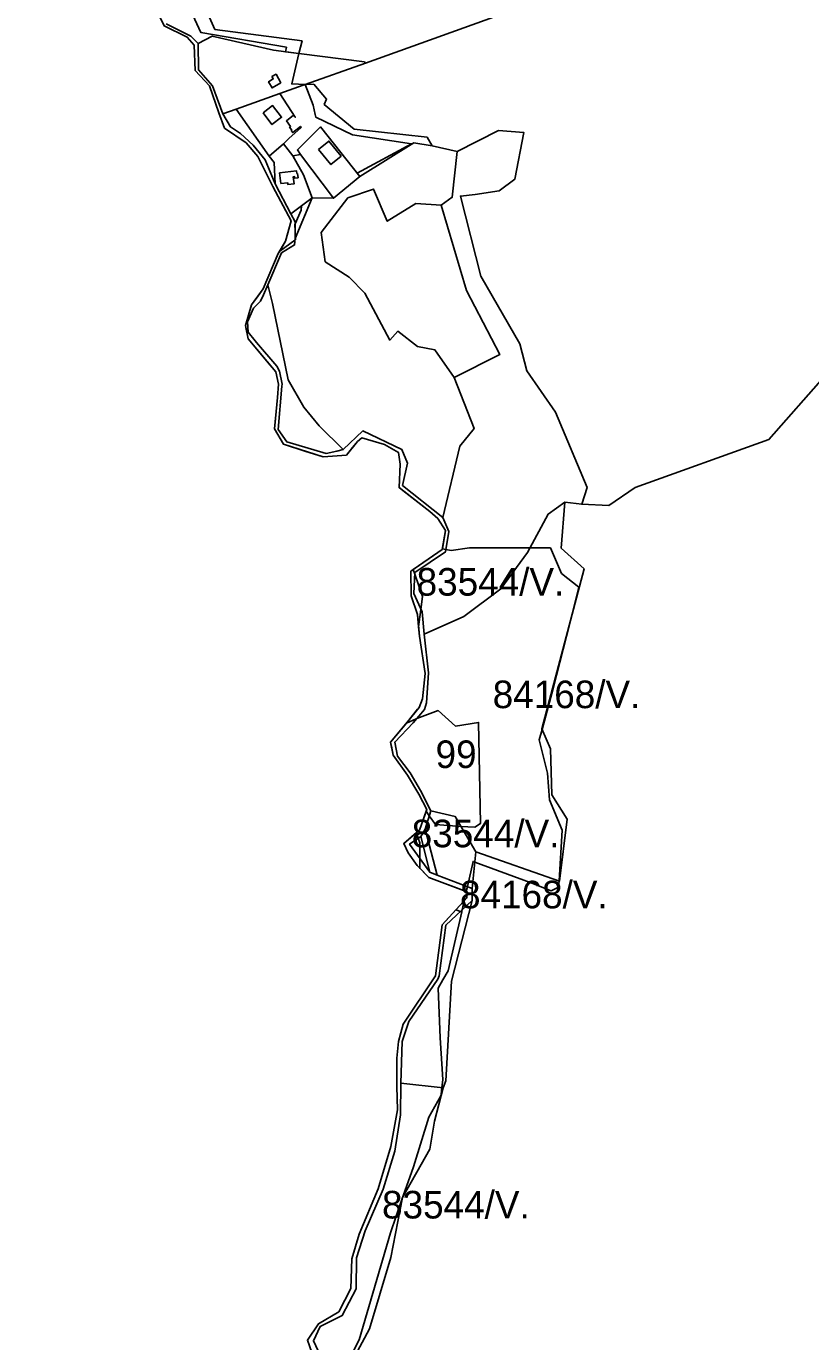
# Model space of a CAD drawing. Extents: x -477304 to -465429, y -1159113 to -1149210.
# Drawn here: x -476469 to -476043, y -1154135 to -1153420 of the extents above; entities that cross this region are included whole.
import ezdxf

# ---------------------------------------------------------------- set-up
doc = ezdxf.new("R2010")
doc.units = 0
for name, color, linetype in [('BPEJ_s', 7, 'Continuous'), ('PUPFL_s', 7, 'Continuous'), ('trav_porost_s', 7, 'Continuous'), ('voda_s', 7, 'Continuous'), ('zahrada_s', 7, 'Continuous')]:
    doc.layers.add(name, color=color, linetype=linetype)

msp = doc.modelspace()

# ---------------------------------------------------------------- linework, layer by layer
at = {"layer": 'BPEJ_s'}
for p, q in [((-476331.66, -1153541.75), (-476331.65, -1153541.75)), ((-476341.64, -1153563.62), (-476343.36, -1153566.03)), ((-476350.28, -1153582.25), (-476350.08, -1153583.28)), ((-476329.6, -1153646.76), (-476317.5, -1153650.64)), ((-476295.43, -1153652.79), (-476292.04, -1153648.55)), ((-476266.79, -1153670.31), (-476264.7, -1153671.95))]:
    msp.add_line(p, q, dxfattribs=at)
for points in [[(-476469.44, -1153302.84), (-476465.62, -1153305.59), (-476462.52, -1153314.71), (-476461.47, -1153317.8), (-476462.31, -1153337.1), (-476459.47, -1153347.25), (-476453.13, -1153354.27), (-476434.77, -1153364.18), (-476417.39, -1153374.78), (-476413.17, -1153379.06), (-476396.78, -1153414.37), (-476394.56, -1153419.33), (-476381.89, -1153425.52), (-476378.24, -1153429.87), (-476377.6, -1153443.54), (-476369.87, -1153451.92), (-476364.68, -1153466.61), (-476361.59, -1153474.95), (-476349.92, -1153482.92), (-476343.55, -1153490.4), (-476335.45, -1153506.67), (-476325.49, -1153525.38), (-476328.44, -1153536.44), (-476331.66, -1153541.75)], [(-476313.98, -1153512.84), (-476302.48, -1153513.07), (-476288.12, -1153501.24), (-476289.5, -1153499.5), (-476260, -1153483.5), (-476292, -1153478.5), (-476312, -1153469), (-476312.32, -1153467.61), (-476313.5, -1153462.5), (-476317.75, -1153451.14), (-476325.15, -1153450.94), (-476321.25, -1153434.31), (-476328.55, -1153433.37), (-476328, -1153431), (-476374.5, -1153423), (-476383.5, -1153403.5)], [(-476383.5, -1153403.5), (-476374.5, -1153423), (-476328, -1153431), (-476328.55, -1153433.37), (-476321.25, -1153434.31), (-476325.15, -1153450.94), (-476317.75, -1153451.14), (-476313.5, -1153462.5), (-476312.32, -1153467.61), (-476312, -1153469), (-476292, -1153478.5), (-476260, -1153483.5), (-476289.5, -1153499.5), (-476288.12, -1153501.24), (-476302.48, -1153513.07), (-476313.98, -1153512.84), (-476319.74, -1153517.13), (-476320, -1153519.5), (-476323.24, -1153526.91), (-476323.5, -1153527.5), (-476323.29, -1153530.85), (-476323.07, -1153534.31), (-476323, -1153535.5), (-476323.4, -1153535.79), (-476331.65, -1153541.75), (-476331.66, -1153541.75), (-476332.5, -1153543.15), (-476340.68, -1153562.28), (-476341.64, -1153563.62)], [(-476331.65, -1153541.75), (-476323.4, -1153535.79), (-476323, -1153535.5), (-476323.07, -1153534.31), (-476323.29, -1153530.85), (-476323.5, -1153527.5), (-476323.24, -1153526.91), (-476320, -1153519.5), (-476319.74, -1153517.13), (-476313.98, -1153512.84)], [(-476343.36, -1153566.03), (-476346.92, -1153571), (-476350.28, -1153582.25)], [(-476350.08, -1153583.28), (-476348.88, -1153589.54), (-476336.83, -1153603.79), (-476333.7, -1153607.49), (-476332.24, -1153614.05), (-476332.85, -1153621.28), (-476333.96, -1153632.7), (-476334.52, -1153638.44), (-476329.6, -1153646.76)], [(-476292.04, -1153648.55), (-476289.45, -1153645.32), (-476287.06, -1153643.2), (-476280.85, -1153645.09), (-476274.67, -1153646.97), (-476267.13, -1153651.17), (-476266.15, -1153657.52), (-476266.79, -1153670.31)], [(-476317.5, -1153650.64), (-476308.09, -1153653.66), (-476295.43, -1153652.79)], [(-476264.7, -1153671.95), (-476250.12, -1153683.41), (-476245.71, -1153687.07), (-476241.45, -1153693.6), (-476243.23, -1153703.64), (-476241.36, -1153703.98), (-476238.5, -1153704.5), (-476228.5, -1153703), (-476195.54, -1153703), (-476184.5, -1153703), (-476178.5, -1153717), (-476169, -1153724.5), (-476174, -1153744.13), (-476183, -1153779.5), (-476188.98, -1153801.84), (-476190.5, -1153807.5), (-476186, -1153825.5), (-476185, -1153840), (-476178, -1153856.5), (-476179.78, -1153884.14), (-476180, -1153887.5), (-476184, -1153889.5), (-476195.5, -1153885), (-476225.55, -1153873.85), (-476226.5, -1153873.5), (-476229.61, -1153887.2), (-476230.21, -1153889.83), (-476229.75, -1153890), (-476229.85, -1153893.33), (-476231.38, -1153895), (-476232.49, -1153899.88), (-476232.58, -1153900.3), (-476232.72, -1153900.93), (-476240, -1153933), (-476242.88, -1153937.97), (-476245.5, -1153942.5), (-476244.5, -1153969.5), (-476243, -1153992), (-476243.51, -1153996.6), (-476243.89, -1154000), (-476244, -1154001), (-476250.5, -1154012.5), (-476259, -1154039.5), (-476264.51, -1154055.36), (-476265.2, -1154057.35), (-476271.5, -1154075.5), (-476288.5, -1154133.5), (-476300, -1154156.5)], [(-476314.26, -1154140.55), (-476316.58, -1154133.74), (-476310.59, -1154124.87), (-476299.56, -1154118.31), (-476292.99, -1154105.63), (-476292.36, -1154089.54), (-476288.4, -1154076.16), (-476278.16, -1154051.5), (-476271.3, -1154028.49), (-476267.65, -1154008.59), (-476267.97, -1153995.89), (-476267.95, -1153980.53), (-476266.98, -1153971.37), (-476264.6, -1153962.05), (-476247.01, -1153935.72), (-476243.39, -1153908.08), (-476235.86, -1153899.88), (-476233.38, -1153900.71), (-476232.72, -1153900.93), (-476240, -1153933), (-476242.88, -1153937.97), (-476245.5, -1153942.5), (-476244.5, -1153969.5), (-476243, -1153992), (-476243.51, -1153996.6), (-476243.89, -1154000), (-476244, -1154001), (-476250.5, -1154012.5), (-476259, -1154039.5), (-476264.51, -1154055.36), (-476265.2, -1154057.35), (-476271.5, -1154075.5), (-476288.5, -1154133.5), (-476300, -1154156.5)]]:
    msp.add_lwpolyline(points, dxfattribs=at)
for points in [[(-476184.5, -1153703), (-476178.5, -1153717), (-476169, -1153724.5), (-476174, -1153744.13), (-476183, -1153779.5), (-476188.98, -1153801.84), (-476190.5, -1153807.5), (-476186, -1153825.5), (-476185, -1153840), (-476178, -1153856.5), (-476179.78, -1153884.14), (-476180, -1153887.5), (-476184, -1153889.5), (-476195.5, -1153885), (-476225.55, -1153873.85), (-476226.5, -1153873.5), (-476229.61, -1153887.2), (-476230.21, -1153889.83), (-476250.63, -1153882.24), (-476255.5, -1153877.23), (-476255.5, -1153871.86), (-476255.5, -1153863.5), (-476256.3, -1153860.82), (-476257.2, -1153857.82), (-476257.2, -1153857.81), (-476255.66, -1153856.52), (-476252.04, -1153846.26), (-476250.34, -1153848.7), (-476247, -1153853.5), (-476233.1, -1153854.47), (-476225.5, -1153855), (-476222.5, -1153853), (-476223.5, -1153798), (-476236, -1153800), (-476245.5, -1153791.5), (-476257.06, -1153795.84), (-476257.5, -1153796), (-476262.73, -1153798.38), (-476262.11, -1153797.64), (-476256.66, -1153790.83), (-476255.82, -1153789.78), (-476254.09, -1153785.08), (-476252.59, -1153771.37), (-476255.67, -1153751.15), (-476256.14, -1153745.96), (-476254.91, -1153736.54), (-476254, -1153729.5), (-476258.23, -1153717.36), (-476259.11, -1153714.85), (-476243.28, -1153703.95), (-476243.23, -1153703.64), (-476241.36, -1153703.98), (-476238.5, -1153704.5), (-476228.5, -1153703), (-476195.54, -1153703)], [(-476254.91, -1153736.54), (-476256.14, -1153745.96), (-476256.74, -1153739.27), (-476260.12, -1153729.15), (-476260.43, -1153715.76), (-476259.11, -1153714.85), (-476258.23, -1153717.36), (-476254, -1153729.5)], [(-476252.04, -1153846.26), (-476251.68, -1153845.24), (-476256.07, -1153836.98), (-476262.17, -1153826.66), (-476269.89, -1153815.72), (-476270.88, -1153810.88), (-476271.34, -1153808.63), (-476262.73, -1153798.38), (-476257.5, -1153796), (-476257.06, -1153795.84), (-476245.5, -1153791.5), (-476236, -1153800), (-476223.5, -1153798), (-476222.5, -1153853), (-476225.5, -1153855), (-476233.1, -1153854.47), (-476247, -1153853.5), (-476250.34, -1153848.7)], [(-476255.5, -1153871.86), (-476255.5, -1153877.23), (-476256.86, -1153875.83), (-476261.88, -1153868.81), (-476264.24, -1153863.72), (-476257.2, -1153857.81), (-476257.2, -1153857.82), (-476256.3, -1153860.82), (-476255.5, -1153863.5)], [(-476232.58, -1153900.3), (-476232.72, -1153900.93), (-476233.38, -1153900.71), (-476235.86, -1153899.88), (-476231.38, -1153895), (-476232.49, -1153899.88)]]:
    msp.add_lwpolyline(points, close=True, dxfattribs=at)
at = {"layer": 'PUPFL_s'}
for points in [[(-476374.39, -1153404.56), (-476352.66, -1153405.48), (-476340.75, -1153395.62), (-476330.21, -1153398.6), (-476316.6, -1153401.84), (-476291.35, -1153405.58), (-476257.17, -1153402.62), (-476217.27, -1153401.74), (-476154.38, -1153379.72), (-476139.88, -1153376.51), (-476120.34, -1153379.11), (-476083.36, -1153366.41), (-476082.77, -1153366.77), (-476285.01, -1153439.63), (-476285.61, -1153438.87), (-476321.25, -1153434.31), (-476319.45, -1153427.4), (-476366.92, -1153421.26)], [(-476253.14, -1153750), (-476254.28, -1153737.93), (-476258.82, -1153727.98), (-476258.19, -1153716.55), (-476241.6, -1153705.3), (-476239.62, -1153694.23), (-476242.91, -1153686.53), (-476233.77, -1153647.74), (-476225.88, -1153638.26), (-476236.79, -1153610.55), (-476211.96, -1153597.98), (-476230.14, -1153563.14), (-476243.89, -1153516.72), (-476237.88, -1153512.5), (-476235.18, -1153487.63), (-476212.73, -1153476.14), (-476198.92, -1153477.35), (-476203.82, -1153502.73), (-476212.39, -1153509.02), (-476225.3, -1153511.01), (-476233.44, -1153511.83), (-476222.33, -1153555.36), (-476201.12, -1153592.18), (-476197.37, -1153606.95), (-476181.77, -1153629.24), (-476164.54, -1153670.32), (-476167.46, -1153679.41), (-476176.7, -1153678.16), (-476185.68, -1153684.75), (-476196.99, -1153705.68), (-476211.47, -1153725.45), (-476231.5, -1153740.34)], [(-476309.17, -1153531.74), (-476306.89, -1153547.56), (-476293.85, -1153555.93), (-476285.32, -1153564.73), (-476271.82, -1153590.14), (-476267.39, -1153585.34), (-476256.69, -1153593.65), (-476247.25, -1153595.5), (-476236.79, -1153610.55), (-476225.88, -1153638.26), (-476233.77, -1153647.74), (-476242.91, -1153686.53), (-476264.81, -1153669.17), (-476262.19, -1153657), (-476265.21, -1153649.58), (-476286.41, -1153639.51), (-476297.08, -1153649.67), (-476310.27, -1153636.72), (-476318.59, -1153626.69), (-476327.06, -1153611.84), (-476335.5, -1153570.35), (-476338.18, -1153560.15), (-476330.64, -1153542.74), (-476323.6, -1153538.43), (-476323.34, -1153534.94), (-476313.98, -1153512.84), (-476318.75, -1153500.26), (-476324.58, -1153490.06), (-476320.27, -1153489.18), (-476302.48, -1153513.07), (-476288.12, -1153501.24), (-476258.77, -1153482.88), (-476248.74, -1153484.62), (-476235.18, -1153487.63), (-476237.88, -1153512.5), (-476243.89, -1153516.72), (-476257.69, -1153515.98), (-476273.17, -1153525.52), (-476280.65, -1153508.04), (-476294.54, -1153512.91)], [(-476309.17, -1153531.74), (-476294.54, -1153512.91), (-476280.65, -1153508.04), (-476273.17, -1153525.52), (-476257.69, -1153515.98), (-476243.89, -1153516.72), (-476230.14, -1153563.14), (-476211.96, -1153597.98), (-476236.79, -1153610.55), (-476247.25, -1153595.5), (-476256.69, -1153593.65), (-476267.39, -1153585.34), (-476271.82, -1153590.14), (-476285.32, -1153564.73), (-476293.85, -1153555.93), (-476306.89, -1153547.56)], [(-476251.85, -1153787.38), (-476250.71, -1153770.96), (-476253.14, -1153750), (-476231.5, -1153740.34), (-476211.47, -1153725.45), (-476196.99, -1153705.68), (-476185.68, -1153684.75), (-476176.7, -1153678.16), (-476178.61, -1153703.23), (-476166.14, -1153714.5), (-476189.18, -1153801.39), (-476184.38, -1153812.39), (-476183.68, -1153837.32), (-476175.43, -1153850.5), (-476179.46, -1153884.25), (-476224.98, -1153868.35), (-476236.19, -1153849.18), (-476249.57, -1153846.12), (-476255.05, -1153834.92), (-476260.76, -1153825.33), (-476267.59, -1153816.27), (-476269.12, -1153808.64), (-476259.03, -1153798.2), (-476253, -1153790.96)], [(-476249.57, -1153846.12), (-476236.19, -1153849.18), (-476224.98, -1153868.35), (-476227.02, -1153888.18), (-476246.04, -1153880.97), (-476252.55, -1153856.08)], [(-476254.98, -1153859.9), (-476250.09, -1153879.43), (-476261.05, -1153864.1)], [(-476242.85, -1153996.68), (-476247.58, -1154014.79), (-476250, -1154029.94), (-476264.97, -1154056.17), (-476271.28, -1154088.83), (-476282.8, -1154127.52), (-476302.66, -1154164.46), (-476317.42, -1154173.65), (-476314.48, -1154161.92), (-476305.29, -1154150.31), (-476309.7, -1154141.92), (-476313.32, -1154134.04), (-476309.62, -1154126.27), (-476297.61, -1154120.33), (-476290.01, -1154105.95), (-476289.96, -1154089.01), (-476285.27, -1154074.36), (-476275.36, -1154051.75), (-476269.12, -1154031.02), (-476266.04, -1154011.2), (-476265.77, -1153994.01)]]:
    msp.add_lwpolyline(points, close=True, dxfattribs=at)
for points in [[(-476034.71, -1153609.09), (-476065.7, -1153644.11), (-476138.37, -1153670.35), (-476152.76, -1153679.98), (-476167.46, -1153679.41), (-476164.54, -1153670.32), (-476181.77, -1153629.24), (-476197.37, -1153606.95), (-476201.12, -1153592.18), (-476222.33, -1153555.36), (-476233.44, -1153511.83), (-476225.3, -1153511.01), (-476212.39, -1153509.02), (-476203.82, -1153502.73), (-476198.92, -1153477.35), (-476212.73, -1153476.14), (-476235.18, -1153487.63), (-476248.74, -1153484.62), (-476251.49, -1153479.8), (-476291.11, -1153475.5), (-476307.41, -1153462), (-476306.29, -1153459.14), (-476313.17, -1153450.96), (-476317.75, -1153451.14), (-476285.01, -1153439.63), (-476082.77, -1153366.77)], [(-476302.66, -1154164.46), (-476282.8, -1154127.52), (-476271.28, -1154088.83), (-476264.97, -1154056.17), (-476250, -1154029.94), (-476247.58, -1154014.79), (-476242.85, -1153996.68), (-476241.39, -1153992.74), (-476238.3, -1153938.61), (-476227.09, -1153894.85), (-476227.02, -1153888.18), (-476224.98, -1153868.35), (-476179.46, -1153884.25), (-476175.43, -1153850.5), (-476183.68, -1153837.32), (-476184.38, -1153812.39), (-476189.18, -1153801.39), (-476166.14, -1153714.5), (-476178.61, -1153703.23), (-476176.7, -1153678.16), (-476167.46, -1153679.41), (-476152.76, -1153679.98), (-476138.37, -1153670.35), (-476065.7, -1153644.11), (-476034.71, -1153609.09)]]:
    msp.add_lwpolyline(points, dxfattribs=at)
at = {"layer": 'trav_porost_s'}
for points in [[(-476325.41, -1153476.21), (-476324.52, -1153477.33), (-476320.37, -1153474.03), (-476320.02, -1153474.66), (-476326.61, -1153480.65), (-476329.65, -1153483.42), (-476337.32, -1153490.26), (-476355.41, -1153464.67), (-476331.65, -1153456.13), (-476323.18, -1153469.05), (-476324.07, -1153467.95), (-476328.05, -1153471.04), (-476325.7, -1153473.97), (-476326.28, -1153474.43), (-476325.08, -1153475.95)], [(-476340.7, -1153466.7), (-476335.85, -1153473), (-476330.66, -1153469.01), (-476335.5, -1153462.7)]]:
    msp.add_lwpolyline(points, close=True, dxfattribs=at)
at = {"layer": 'voda_s'}
for points in [[(-476393.35, -1153418.2), (-476379.91, -1153424.86), (-476376.06, -1153428.96), (-476375.81, -1153443.28), (-476368.25, -1153451.9), (-476362.51, -1153467.22), (-476358.49, -1153474.24), (-476353.06, -1153477.77), (-476346.01, -1153484.15), (-476339.53, -1153492.24), (-476334.1, -1153505.22), (-476325.66, -1153521.55), (-476323.23, -1153525.8), (-476323.34, -1153534.94), (-476323.6, -1153538.43), (-476330.64, -1153542.74), (-476338.18, -1153560.15), (-476340.48, -1153565.47), (-476342.04, -1153569.07), (-476345.92, -1153572.87), (-476349.15, -1153580.29), (-476348.75, -1153585.83), (-476345.08, -1153590.55), (-476344.24, -1153591.53), (-476333.29, -1153604.35), (-476331.75, -1153606.97), (-476330.32, -1153614.13), (-476330.42, -1153615.23), (-476332.58, -1153638.66), (-476327.82, -1153645.4), (-476306.4, -1153651.77), (-476300.67, -1153650.48), (-476297.08, -1153649.67), (-476286.41, -1153639.51), (-476265.21, -1153649.58), (-476262.19, -1153657), (-476264.81, -1153669.17), (-476242.91, -1153686.53), (-476239.62, -1153694.23), (-476241.6, -1153705.3), (-476258.19, -1153716.55), (-476258.82, -1153727.98), (-476254.28, -1153737.93), (-476253.14, -1153750), (-476250.71, -1153770.96), (-476251.85, -1153787.38), (-476253, -1153790.96), (-476259.03, -1153798.2), (-476269.12, -1153808.64), (-476267.59, -1153816.27), (-476260.76, -1153825.33), (-476255.05, -1153834.92), (-476249.57, -1153846.12), (-476252.55, -1153856.08), (-476254.98, -1153859.9), (-476261.05, -1153864.1)], [(-476314.26, -1154140.55), (-476316.58, -1154133.74), (-476310.59, -1154124.87), (-476299.56, -1154118.31), (-476292.99, -1154105.63), (-476292.36, -1154089.54), (-476288.4, -1154076.16), (-476278.16, -1154051.5), (-476271.3, -1154028.49), (-476267.65, -1154008.59), (-476267.97, -1153995.89), (-476267.95, -1153980.53), (-476266.98, -1153971.37), (-476264.6, -1153962.05), (-476247.01, -1153935.72), (-476243.39, -1153908.08), (-476229.85, -1153893.33), (-476229.75, -1153890), (-476250.63, -1153882.24), (-476256.86, -1153875.83), (-476261.88, -1153868.81), (-476264.24, -1153863.72), (-476255.66, -1153856.52), (-476251.68, -1153845.24), (-476256.07, -1153836.98), (-476262.17, -1153826.66), (-476269.89, -1153815.72), (-476271.34, -1153808.63), (-476262.11, -1153797.64), (-476255.82, -1153789.78), (-476254.09, -1153785.08), (-476252.59, -1153771.37), (-476255.67, -1153751.15), (-476256.74, -1153739.27), (-476260.12, -1153729.15), (-476260.43, -1153715.76), (-476243.28, -1153703.95), (-476241.45, -1153693.6), (-476245.71, -1153687.07), (-476250.12, -1153683.41), (-476266.79, -1153670.31), (-476266.15, -1153657.52), (-476267.13, -1153651.17), (-476274.67, -1153646.97), (-476287.06, -1153643.2), (-476289.45, -1153645.32), (-476295.43, -1153652.79), (-476308.09, -1153653.66), (-476329.6, -1153646.76), (-476334.52, -1153638.44), (-476332.85, -1153621.28), (-476332.24, -1153614.05), (-476333.7, -1153607.49), (-476348.88, -1153589.54), (-476350.28, -1153582.25), (-476346.92, -1153571), (-476340.68, -1153562.28), (-476332.5, -1153543.15), (-476328.44, -1153536.44), (-476325.49, -1153525.38), (-476335.45, -1153506.67), (-476343.55, -1153490.4), (-476349.92, -1153482.92), (-476361.59, -1153474.95), (-476364.68, -1153466.61), (-476369.87, -1153451.92), (-476377.6, -1153443.54), (-476378.24, -1153429.87), (-476381.89, -1153425.52), (-476394.56, -1153419.33)], [(-476261.05, -1153864.1), (-476250.09, -1153879.43), (-476246.04, -1153880.97), (-476227.02, -1153888.18), (-476227.09, -1153894.85), (-476241.36, -1153908.15), (-476244.91, -1153935.7), (-476245.7, -1153937.58), (-476261.43, -1153960.6), (-476264.99, -1153971.4), (-476265.77, -1153994.01), (-476266.04, -1154011.2), (-476269.12, -1154031.02), (-476275.36, -1154051.75), (-476285.27, -1154074.36), (-476289.96, -1154089.01), (-476290.01, -1154105.95), (-476297.61, -1154120.33), (-476309.62, -1154126.27), (-476313.32, -1154134.04), (-476309.7, -1154141.92)]]:
    msp.add_lwpolyline(points, dxfattribs=at)
at = {"layer": 'zahrada_s'}
for points in [[(-476362.51, -1153467.22), (-476368.25, -1153451.9), (-476375.81, -1153443.28), (-476376.06, -1153428.96), (-476368.33, -1153424.93), (-476335.11, -1153432.53), (-476321.25, -1153434.31), (-476325.15, -1153450.94), (-476317.75, -1153451.14), (-476318.84, -1153451.52), (-476331.65, -1153456.13), (-476355.41, -1153464.67)], [(-476335.86, -1153446.89), (-476335.13, -1153448.21), (-476337.75, -1153449.75), (-476335.79, -1153453.08), (-476331.05, -1153450.29), (-476333.64, -1153445.65)], [(-476302.48, -1153513.07), (-476320.27, -1153489.18), (-476322.05, -1153486.79), (-476309.49, -1153474.25), (-476288.12, -1153501.24)], [(-476310.49, -1153486.55), (-476303.85, -1153494.78), (-476298.29, -1153490.17), (-476304.93, -1153481.94)], [(-476334.1, -1153505.22), (-476334.66, -1153493.64), (-476337.32, -1153490.26), (-476329.65, -1153483.42), (-476324.58, -1153490.06), (-476318.75, -1153500.26), (-476313.98, -1153512.84), (-476325.66, -1153521.55)], [(-476321.98, -1153499.52), (-476322.3, -1153499.55), (-476322.46, -1153498.16), (-476331.69, -1153499.25), (-476331.01, -1153505.02), (-476327.28, -1153504.58), (-476327.15, -1153505.63), (-476323.85, -1153505.24), (-476324.32, -1153501.35), (-476323.59, -1153501.27), (-476323.49, -1153502.11), (-476321.7, -1153501.9)]]:
    msp.add_lwpolyline(points, close=True, dxfattribs=at)

# ---------------------------------------------------------------- texts
at = {"layer": 'BPEJ_s'}
for s, p in [('83544/V.', (-476257.22, -1153729.06)), ('84168/V.', (-476215.86, -1153790.22)), ('99', (-476246.92, -1153822.77)), ('83544/V.', (-476259.87, -1153865.84)), ('84168/V.', (-476233.62, -1153899.03)), ('83544/V.', (-476276.02, -1154067.62))]:
    msp.add_text(s, height=15, dxfattribs=at).set_placement(p)

doc.saveas('drawing.dxf')
